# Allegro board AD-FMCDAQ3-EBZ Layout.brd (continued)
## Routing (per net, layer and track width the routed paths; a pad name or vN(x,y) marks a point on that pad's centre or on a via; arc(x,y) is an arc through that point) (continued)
P1V7: length 57.5
  TOP w0.305: U17.16 38,13.68 ; U17.16 U17.15 36.86,12.84 ; U17.16 37.51,12.84 ; U17.3 39.27,15.9 ; U17.3 U17.4 ; U17.3 U17.2 ; U19.1 U19.2 ; U19.1 16.47,63.53 ; U19.1 15.63,63.04 ; U19.2 U19.3 ; U19.2 15.63,62.39 ; U17.4 38.43,17.05 ; U17.4 39.27,16.55 ; U19.3 U19.4 ; U19.3 15.63,61.74 ; U19.4 15.63,61.09 ; U19.4 16.47,60.59 ; U17.2 39.27,15.25 ; U17.2 U17.1 ; 18.04,64.8 U19.15 U19.16 ; 16.9,63.96 U19.16 ; U19.16 17.39,64.8 ; U17.1 39.27,14.6 ; U17.1 38.43,14.11
  TOP w0.508: C167.P 41.64,14.18 ; C167.P 40.72,12.85 ; C167.P 39.81,14.18 ; C186.P 15.09,63.46 ; C186.P 14.18,64.79 ; C186.P 13.26,63.46
  L2_AGND w0.254: v1(43.89,67.13) v2(43.89,66.63)
  BOTTOM w0.508: CO5.2 59.95,31.2 ; CO5.2 58.63,30.08 ; CO5.2 58.63,32.32 ; CO5.2 57.31,31.2 ; RFB2.2 51.58,27.39 ; RFB2.2 51.58,25.36 ; RFB2.2 50.61,26.37 ; 48.6,27.71 TP3.1 ; TP3.1 49.29,28.41 ; TP3.1 48.6,29.11 ; TP3.1 47.9,28.41 ; 54.51,31.2 CO6.2 ; CO6.2 55.83,30.08 ; CO6.2 55.83,32.32 ; CO6.2 57.16,31.2 ; 48.92,31.2 CO8.2 ; CO8.2 51.57,31.2 ; CO8.2 50.25,32.32 ; CO8.2 50.25,30.08 ; 51.72,31.2 CO7.2 ; CO7.2 54.36,31.2 ; CO7.2 53.04,30.08 ; CO7.2 53.04,32.32
  BOTTOM w0.762: L12.2 59.9,29.76 ; L12.2 62.41,29.09 ; L12.2 59.9,27.68 ; L12.2 57.38,29.09
  vias: v1(13.8,64.22) v1(13.8,63.46) v1(13.8,62.7) v1(14.56,64.22) v1(14.56,63.46) v1(14.56,62.7) v1(39.58,12.28) v1(39.58,11.52) v1(40.34,12.28) v1(40.34,11.52) v1(41.1,12.28) v1(41.1,11.52) v1(41.86,12.28) v1(41.86,11.52) v2(12.27,64.22) v2(12.27,63.46) v2(12.27,62.7) v2(13.04,64.22) v2(13.04,63.46) v2(13.04,62.7) v2(37.67,11.01) v2(37.67,10.25) v2(38.44,11.01) v2(38.44,10.25) v2(39.2,11.01) v2(39.2,10.25) v2(39.96,11.01) v2(39.96,10.25) v2(47.96,34.38) v2(47.96,33.74) v2(47.96,33.11) v2(48.6,34.38) v2(48.6,33.74) v2(48.6,33.11) v2(49.23,34.38) v2(49.23,33.74) v2(49.23,33.11) v3(48.09,32.34) v3(48.09,31.71) v3(48.09,31.07) v3(48.09,30.44) v3(48.09,29.8) v3(48.72,32.34) v3(48.72,31.71) v3(48.72,31.07) v3(48.72,30.44) v3(48.72,29.8)
P2V5_EN: length 97.4
  TOP w0.152: v1(48.47,54.19) 48.47,52.16 48.71,51.92 U4.4
  TOP w0.305: U5.4 v4(8.15,7.24)
  L2_AGND w0.152: v1(48.47,54.19) v2(48.47,55.2)
  L3_SIG w0.254: v2(6.56,51.65) 6.56,43.77 10.94,39.39 10.94,11.45 8.72,9.23 8.72,7.8 v4(8.15,7.24)
  L8_SIG w0.254: v2(6.56,51.65) 8.21,53.3 23.7,53.3 24.72,54.31 28.15,54.31 31.09,57.26 33.79,57.26 34.57,56.47 43.01,56.47 44.28,55.2 v2(48.47,55.2)
P3V3_CLK_OUT: length 28.3
  TOP w0.254: C63.2 v1(37.86,33.23) 37.17,33.23 37.14,33.26 U7.42 ; U7.45 36.53,34.76 37.55,34.76 37.55,34.76 v1(37.86,34.76) C83.2 ; C59.2 v1(37.86,39.33) 37.29,39.33 37.22,39.26 U7.54 ; C66.2 v1(37.86,31.71) 37.81,31.76 36.53,31.76 U7.39 ; U7.27 31.33,29.47 C70.2 ; U7.48 36.53,36.26 37.55,36.26 37.57,36.28 v1(37.86,36.28) C82.2 ; C80.2 37.93,37.74 v1(37.86,37.74) 37.55,37.74 37.53,37.76 U7.51 ; U7.36 35.82,30.05 35.82,29.63
  TOP w0.305: U7.66 v4(30.33,39.11) ; v1(33.23,28.74) 32.86,28.74 C72.2 32.82,28.75 32.82,29.21 U7.30 ; U7.69 v4(28.83,39.11) ; U7.63 v4(31.83,39.11) ; 35.82,29.63 36.15,29.3 36.15,28.72 v1(36.28,28.72) ; U7.33 34.33,29.4 34.05,29.13 v1(34.05,28.72) ; U7.60 v4(33.33,39.11) ; C70.2 v1(32.11,28.74)
  TOP w1.016: C24.1 v1(37.29,25.61) 35.84,25.61 E11.2
  L2_AGND w0.254: v1(37.86,31.71) v2(37.36,31.77) ; v2(37.36,34.76) v1(37.86,34.76) ; v2(37.36,36.28) v1(37.86,36.28) ; v2(37.36,33.23) v1(37.86,33.23) ; v2(37.36,39.33) v1(37.86,39.33) ; v1(36.28,28.72) v2(36.28,29.17) ; v1(37.86,37.74) v2(37.36,37.74)
  L2_AGND w0.305: v2(32.11,29.26) v1(32.11,28.74) ; v2(33.23,29.26) v1(33.23,28.74)
  L2_AGND w0.356: v2(34.05,28.22) v1(34.05,28.72)
  BOTTOM w0.305: v4(30.33,39.11) 30.24,39.19 C78.2 ; C32.2 33.29,39.14 v4(33.33,39.11) ; v4(28.83,39.11) 28.85,39.13 C30.2 ; v4(31.83,39.11) 31.64,39.3 C79.2
  vias: v1(37.29,26.12) v1(37.29,25.1) v1(37.93,26.12) v1(37.93,25.61) v1(37.93,25.1) v2(36.4,27.77) v2(37.17,27.77) v2(37.93,27.77)
P3V3_CLK_PLL: length 9.4
  TOP w0.254: U7.16 26.63,31.76 25.79,31.76 25.61,31.58 C81.2 v1(25.23,31.58)
  TOP w0.305: v1(24.91,35.07) C71.2 25.54,35.07 25.86,34.76 U7.10 ; U7.1 26.63,39.58 v4(26.43,39.77) ; U7.20 27.83,29.04 C64.2 27.16,28.72 v1(27.13,28.75) ; U7.72 27.33,39.58 27.39,39.52 27.39,39.2 v4(27.48,39.11)
  L2_AGND w0.254: v1(25.23,31.58) v2(25.74,31.58)
  L2_AGND w0.305: v1(27.13,28.75) v2(27.13,29.22) ; v1(24.91,35.07) v2(25.42,35.07)
  BOTTOM w0.305: v4(27.48,39.11) 27.26,38.89 C73.2 ; C60.2 26.5,39.27 26.5,39.7 v4(26.43,39.77)
  vias: v1(22.18,29.8) v1(22.18,29.3) v1(22.69,29.8) v1(22.69,29.3) v2(21.29,28.79) v2(21.93,28.79) v2(22.56,28.79)
P3V6: length 87
  TOP w0.254: 7.45,42.76 7.45,42.88 7.66,43.1 7.88,43.1 8.05,43.27 8.59,43.27
  TOP w0.305: 11.23,24.1 U8.8 11.97,23.63 ; v1(53.17,52.03) 53.06,51.92 U4.3 ; 11.23,24.6 U8.7
  TOP w0.508: 8.74,23.52 C149.1 ; C149.1 9.86,24.48 ; C149.1 10.98,23.52 ; 49.42,39.93 U22.1 49.99,38.85 ; C262.1 50.86,41.93 ; C262.1 49.74,40.97 ; C262.1 48.62,41.93 ; C48.1 9.23,49.12 ; C48.1 8.11,48.15 ; C48.1 10.34,48.15 ; C34.1 12.88,48.15 ; C34.1 10.65,48.15 ; C34.1 11.77,49.12 ; 47.52,39.93 U22.3 46.95,38.85 ; 8.27,50.38 U10.8 ; U10.8 10.43,50.38 ; U10.8 9.35,49.74 ; C166.1 7.45,24.48 ; C166.1 8.57,23.52 ; C166.1 6.33,23.52 ; C163.1 48.32,41.93 ; C163.1 47.2,40.97 ; C163.1 46.08,41.93 ; 9.35,54.19 7.96,54.19
  L2_AGND w0.254: v1(54.56,67.13) v2(54.56,66.63) ; v1(53.17,52.03) v2(53.68,52.03)
  L3_SIG w0.508: v2(54.56,66.63) 53.04,65.11 53.04,59.78 54.06,58.76 54.06,57.11 53.68,56.73 v2(53.68,52.03)
  BOTTOM w0.508: 53.48,7.86 C152.1 ; C152.1 52.52,8.98 ; C152.1 53.48,10.09 ; 49.99,10.63 U11.5 51.07,9.99 ; 53.48,5.32 C18.1 ; C18.1 53.48,7.55 ; C18.1 52.52,6.44 ; 51.64,47.46 RFB1.2 52.98,48.92 ; 49.99,5.55 U11.8 51.07,6.18
  BOTTOM w0.635: CO4.2 54.74,50.63 ; CO4.2 52.1,50.63 ; CO4.2 53.42,49.51 ; CO4.2 53.42,51.75 ; 57.69,50.63 CO2.2 ; CO2.2 60.33,50.63 ; CO2.2 59.01,51.75 ; CO2.2 59.01,49.51 ; TP2.1 48.98,49.43 ; TP2.1 48.28,48.73 ; TP2.1 48.98,48.03 ; TP2.1 49.68,48.73 ; CO3.2 56.22,51.75 ; CO3.2 54.89,50.63 ; CO3.2 57.54,50.63 ; CO3.2 56.22,49.51 ; 60.48,50.63 CO1.2 ; CO1.2 61.8,49.51 ; CO1.2 61.8,51.75 ; CO1.2 63.12,50.63 ; L11.2 61.83,49.3 ; L11.2 61.07,47.71 ; L11.2 62.59,47.71
  vias: v1(6.18,25.61) v1(6.18,24.85) v1(6.94,25.61) v1(6.94,24.85) v1(7.7,25.61) v1(7.7,24.85) v1(8.72,48.47) v1(8.72,47.84) v1(9.73,48.47) v1(9.73,47.84) v1(11.26,48.47) v1(11.26,47.84) v1(12.27,48.47) v1(12.27,47.84) v1(49.23,40.22) v1(49.48,40.85) v1(50.12,40.85) v1(50.12,40.34) v1(50.12,39.84) v1(50.75,40.85) v1(50.75,40.34) v1(50.75,39.84) v2(6.18,24.22) v2(6.18,23.45) v2(6.94,24.22) v2(6.94,23.45) v2(7.7,24.22) v2(7.7,23.45) v2(8.72,49.11) v2(9.48,49.11) v2(10.24,49.11) v2(11,49.11) v2(11.77,49.11) v2(12.53,49.11) v2(47.96,41.11) v2(47.96,40.34) v2(47.96,39.58) v2(48.34,53.3) v2(48.34,52.54) v2(48.34,51.77) v2(48.72,41.11) v2(48.72,40.34) v2(48.72,39.58) v2(49.1,53.3) v2(49.1,52.54) v2(49.87,53.3) v2(49.87,52.54) v2(50.63,53.3) v2(50.63,52.54) v2(52.79,10.88) v2(52.79,10.12) v2(52.79,9.36) v2(53.55,10.88) v2(53.55,10.12) v2(53.55,9.36) v3(48.98,51.77) v3(48.98,51.01) v3(48.98,50.25) v3(49.74,51.77) v3(49.74,51.01) v3(49.74,50.25) v3(50.5,51.77) v3(50.5,51.01) v3(50.5,50.25) v3(51.26,10.88) v3(51.26,10.12) v3(51.26,9.36) v3(51.26,8.59) v3(52.02,10.88) v3(52.02,10.12) v3(52.02,9.36) v3(52.02,8.59) v4(6.69,42.76) v4(8.72,43.01) v4(9.48,43.01) v4(10.11,44.54) v4(10.11,43.77)
VINA1_N: length 10.3
  BOTTOM w0.254: 15.19,28.14 15.19,27.9 15.32,27.77 16.33,27.77 16.46,27.64 T100.5 ; 15.19,28.14 13.29,28.14 13.02,27.87 13.01,27.87 12.27,27.13 T101.1 ; 15.19,28.14 18.46,28.14 C187.1
VINA1_P: length 10
  BOTTOM w0.254: T100.3 13.92,29.17 14.05,29.04 15.07,29.04 15.19,28.91 15.19,28.65 ; 15.19,28.65 13.35,28.65 12.33,29.67 T101.3 ; 15.19,28.65 18.25,28.65 18.39,28.79 C108.1
VINA_N: length 2.8
  BOTTOM w0.203: U100.5 23.62,25.07 23.62,26.05 23.35,26.32 23.35,26.74 C196.1
  BOTTOM w0.254: C196.1 23.32,26.9 23.32,27.53 R109.2
VINA_P: length 2.8
  BOTTOM w0.203: U100.6 24.08,25.07 24.08,26.24 23.83,26.48 23.83,26.77 C196.2
  BOTTOM w0.254: C196.2 23.83,26.9 23.83,27.53 R108.2
VINB1_N: length 10.4
  BOTTOM w0.254: C118.1 18.65,12.46 18.07,13.04 15.19,13.04 ; T102.3 13.92,13.55 14.05,13.42 15.07,13.42 15.19,13.29 15.19,13.04 ; T103.3 12.15,14.05 13.16,13.04 15.19,13.04
VINB1_P: length 9.9
  BOTTOM w0.254: T103.1 12.14,11.51 13.16,12.53 15.19,12.53 ; 15.19,12.53 17.86,12.53 C188.1 ; 15.19,12.53 15.19,12.28 15.32,12.15 16.33,12.15 16.46,12.02 T102.5
VINB_N: length 2.3
  BOTTOM w0.203: C198.2 23.61,14.73 23.61,15.99 U100.44
  BOTTOM w0.254: R126.2 23.58,13.99 23.58,14.56 C198.2
VINB_P: length 2.3
  BOTTOM w0.203: U100.43 24.07,15.98 24.07,14.7 C198.1
  BOTTOM w0.254: C198.1 24.08,14.56 24.08,13.99 R127.2
3P3_SUP: length 85
  TOP w0.254: 71.07,43.65 71.09,43.63 U12.23 ; 71.07,43.65 C234.1 ; 71.07,43.65 71.07,43.27 71.21,43.13 U12.24 ; U13.24 71.21,28.78 71.07,28.91 71.07,29.3 ; U13.23 71.09,29.28 71.07,29.3 ; U9.6 73.19,19.56 v1(72.73,20.02) ; 71.07,29.3 C233.1
  TOP w0.508: 49.55,32.5 C261.1 ; C261.1 49.55,34.73 ; C261.1 v1(50.75,33.61) ; 48.85,36.51 U22.5 ; U22.5 49.99,36.51 ; U22.5 49.42,35.43 ; C68.P 43.83,14.63 45.36,14.63 C25.1 U14.1 ; U15.1 44.25,24.34 44.53,24.62 C28.1 45.04,26.76 v1(45.04,27.9)
  L2_AGND w0.254: v1(72.73,20.02) v2(72.09,20.02) ; v1(71.07,31.71) v2(71.71,31.07) ; v1(43.39,13.55) 43.39,12.53 v2(43.64,12.28) ; v1(43.9,53.3) v2(45.93,53.3) ; v1(71.07,46.06) v2(71.07,45.42)
  L2_AGND w0.305: v1(43.39,13.55) v1(43.39,14.82) ; v1(45.04,29.17) v1(45.04,27.9) v2(44.28,27.9)
  L3_SIG w0.305: v2(45.93,53.3) 45.93,51.9 47.2,50.63 47.2,38.06 50.37,34.88 v2(50.37,32.22) v2(50.37,31.33) ; v2(72.09,20.02) 71.71,20.41 v2(71.71,31.07) 71.33,31.45 71.33,39.71 71.71,40.09 71.71,44.79 v2(71.07,45.42)
  vias: v1(50.75,34.12) v1(50.75,33.11) v1(51.64,34.12) v1(51.64,33.61) v1(51.64,33.11) v2(49.48,32.22) v2(49.48,31.33)
3P3_XO: length 6.2
  TOP w0.381: v1(10.24,36.66) 10.3,36.72 C126.1
  TOP w0.508: Y1.6 12.07,36.66 v1(10.24,36.66) 10.24,34.88
  L2_AGND w0.305: v2(10.24,36.03) v1(10.24,36.66)
ADC_1P0: length 4.9
  L9_AGND w0.152: v3(27.1,25.71) 26.56,26.25 26.56,26.82 26.91,27.17 27.05,27.17 27.32,27.45 27.32,27.9 v3(26.88,28.34)
  BOTTOM w0.152: U100.12 v3(27.1,25.71) ; v3(26.88,28.34) C100.1
ADC_1P2_AVDD: length 21.3
  TOP w1.27: 25.23,6.94 v1(24.85,6.94) 23.33,6.94 E1.2
  L9_AGND w0.254: v3(20.4,26.12) v2(20.78,25.68) v3(21.16,26.12) ; v3(19.77,22.81) v2(20.21,22.5) ; v3(19.77,25.04) v2(20.21,24.85) ; v3(19.77,18.25) v2(20.27,18.25) ; v3(19.77,15.96) v2(20.27,15.96) ; v3(19.77,19.77) v2(20.27,19.77) ; v3(20.97,14.63) v2(21.35,14.18) v3(21.73,14.63)
  BOTTOM w0.254: C138.1 19.76,19.76 v3(19.77,19.77) 20.82,19.77 U100.55 ; U100.2 22.1,25.49 21.8,25.79 21.49,25.79 v3(21.16,26.12) 21.04,26.25 C135.1 ; 19.64,15.96 v3(19.77,15.96) 20.58,16.78 U100.49 ; C144.1 20.4,26.31 v3(20.4,26.12) 21.16,25.36 21.48,25.36 21.6,25.24 U100.1 ; 19.64,25.04 v3(19.77,25.04) 20.53,24.28 U100.64 ; 19.64,22.75 19.71,22.75 v3(19.77,22.81) 19.8,22.78 U100.61 ; U100.52 19.67,18.28 19.64,18.25
  BOTTOM w0.305: U100.47 22.1,15.24 21.93,15.07 C136.1 v3(21.73,14.63) ; U100.48 21.6,15.51 21.16,15.07 C145.1 v3(20.97,14.63)
  vias: v1(24.85,7.58) v1(24.85,6.31) v1(25.61,7.58) v1(25.61,6.94) v1(25.61,6.31) v2(24.21,7.58) v2(24.21,6.94) v2(24.21,6.31)
ADC_1P2_AVDD_SR: length 20.6
  TOP w1.27: 25.23,11.64 23.34,11.64 E2.2
  L3_SIG w0.508: v2(25.74,10.5) v2(25.1,10.5) 23.97,10.5 21.11,13.36 20.71,13.36 20.34,13.73 20.34,14.13 17.86,16.61 17.86,19.77 18.88,20.79 v2(20.27,20.79)
  L9_AGND w0.254: v3(19.77,20.79) v2(20.27,20.79)
  BOTTOM w0.254: U100.57 19.78,20.78 v3(19.77,20.79) 19.64,20.79
  vias: v1(24.72,11.9) v1(24.72,11.13) v1(25.35,11.9) v1(25.35,11.13)
ADC_1P2_DRVDD: length 12.4
  TOP w1.27: C232.1 v1(45.42,6.94) 43.92,6.94 E9.2
  L9_AGND w0.254: v3(33.61,16.34) v2(33.61,16.98) ; v3(33.61,25.1) v2(33.61,24.47)
  BOTTOM w0.254: U100.19 30.51,23.28 31.58,24.34 C209.1 C211.1 32.91,24.41 v3(33.61,25.1) ; U100.30 30.52,17.78 31.52,16.78 C210.1 C212.1 33.17,16.78 v3(33.61,16.34)
  vias: v1(45.42,6.31) v1(46.18,6.94) v1(46.18,6.31) v2(45.42,7.71) v2(46.18,7.71)
ADC_1P2_DVDD: length 7.8
  TOP w1.27: E3.2 33.63,6.94 v1(35.13,6.94) C227.1
  L9_AGND w0.254: v3(29.67,14.63) 28.72,14.63 v2(28.66,14.69) ; v3(29.35,26.31) 29.64,26.03 v2(30.11,26.03)
  BOTTOM w0.254: v3(29.35,26.31) C207.1 29.16,26.18 28.6,25.62 U100.15 ; U100.34 28.6,15.56 29.53,14.63 C153.1 v3(29.67,14.63)
  vias: v1(35.13,6.31) v1(35.9,6.94) v1(35.9,6.31) v2(35.13,7.71) v2(35.9,7.71)
ADC_2P5_AVDD: length 94
  TOP w1.27: E17.2 17.88,15.47 C96.P
  L2_AGND w0.254: v1(43.9,63.97) v2(43.39,63.97)
  L3_SIG w0.305: v2(25.67,26.12) 23.39,28.41 23.39,36.09 20.97,38.5 20.97,50.95 22.18,52.16 23.07,52.16 25.1,54.19 25.1,57.62 24.34,58.38 24.34,62.06 v2(25.1,62.82)
  L8_SIG w0.305: v2(43.39,63.97) 42.25,62.82 v2(25.1,62.82)
  L9_AGND w0.254: v3(26.12,26.69) 26.12,26.56 v2(25.67,26.12) 25.34,26.59 v3(25.35,26.69) ; v3(19.77,16.72) v2(20.21,17.1) v3(19.77,17.48) ; v3(27.77,26.76) v2(27.39,26.31) v3(27.07,26.76) ; v3(19.77,23.52) v2(20.21,23.9) v3(19.77,24.28) ; v2(26.74,14.11) v3(26.74,14.63) ; v3(22.5,14.63) v2(22.5,14.14) ; v3(26,14.63) v2(25.62,14.11) v3(25.25,14.63) ; v3(21.93,26.25) v2(21.93,25.55)
  BOTTOM w0.229: 26.88,26.76 26.88,26.73 26.18,26.03 26.18,25.93 26.1,25.85 U100.10
  BOTTOM w0.254: 19.64,17.48 v3(19.77,17.48) 20.06,17.78 U100.51 ; U100.3 22.6,25.53 21.93,26.2 v3(21.93,26.25) 21.8,26.37 C173.1 ; U100.39 26.1,15.28 26.56,14.82 C177.1 v3(26.74,14.63) ; 19.64,24.28 v3(19.77,24.28) 20.27,23.78 U100.63 ; U100.62 20.01,23.28 v3(19.77,23.52) 19.64,23.52 ; v3(25.25,14.63) C129.1 25.1,14.69 U100.41 ; U100.9 25.6,26.17 v3(26.12,26.69) C175.1 ; U100.40 25.6,14.99 25.8,14.79 C179.1 v3(26,14.63) ; C123.1 v3(25.35,26.69) 25.1,26.44 U100.8 ; U100.11 26.6,25.86 26.99,26.25 27.26,26.25 27.64,26.63 27.64,26.76 v3(27.77,26.76) ; v3(27.07,26.76) 26.88,26.76 ; 19.64,16.72 v3(19.77,16.72) 20.32,17.28 U100.50
  BOTTOM w0.305: v3(22.5,14.63) C130.1 22.6,14.72 U100.46
  vias: v1(17.35,16.09) v1(17.35,15.33) v1(17.86,16.09) v1(17.86,15.33) v1(18.37,16.09) v1(18.37,15.33) v2(17.99,14.69) v2(18.75,14.69) v2(18.75,13.93)
ADC_3P3_AVDD: length 10.7
  TOP w0.254: C143.1 v1(22.69,14.82)
  TOP w0.305: C142.1 v1(25.04,14.82)
  TOP w1.27: E20.2 v1(29.54,3.63) C181.1
  L2_AGND w0.305: v1(25.04,14.82) v2(25.11,15.4) ; v1(22.69,14.82) v2(22.59,15.39)
  L9_AGND w0.254: v3(22.69,26.25) v2(22.69,25.55) ; v3(24.6,15.4) v2(25.11,15.4) ; v3(24.59,26.18) v2(24.59,25.55) ; v3(23.1,15.39) v2(22.59,15.39)
  BOTTOM w0.254: U100.7 24.6,26.18 v3(24.59,26.18) C141.1 ; U100.45 v3(23.1,15.39) ; U100.4 23.1,25.84 v3(22.69,26.25) 22.56,26.37 C140.1 ; U100.42 v3(24.6,15.4)
  vias: v1(29.54,3) v1(30.43,3.63) v1(30.43,3) v2(29.55,4.4) v2(30.43,4.4)
ADC_3P3_SPIVDD: length 7
  TOP w1.27: C220.1 v1(36.4,3.63) E21.2
  L9_AGND w0.254: v3(27.51,14.61) 27.51,14.11 v2(27.53,14.09) ; v3(28.59,26.31) v2(28.85,25.74)
  BOTTOM w0.254: U100.13 27.6,25.86 27.98,26.25 28.34,26.25 C150.1 v3(28.59,26.31) ; U100.38 26.6,15.48 27.32,14.75 C151.1 27.5,14.63 v3(27.51,14.61)
  vias: v1(35.51,4.27) v1(35.51,3.63) v1(35.51,3) v1(36.4,4.27) v1(36.4,3) v2(35.51,4.91) v2(36.4,4.91)
ADC_CLK1_N: length 1.4
  TOP w0.254: C40.1 30.82,28.85 30.82,30.05 U7.26
ADC_CLK1_P: length 1.4
  TOP w0.254: U7.25 30.31,30.04 30.31,28.85 C41.1
ADC_CLK_FMC1_N: length 2.8
  TOP w0.203: U7.53 36.55,38.74 39.18,38.74 C168.1
ADC_CLK_FMC1_P: length 2.8
  TOP w0.203: C162.1 39.16,38.28 36.55,38.28 U7.52
ADC_CLK_FMC_N: length 30.4
  TOP w0.254: v4(42.91,29.42) 42.74,29.26 42.24,29.26 40.74,30.76 39.96,30.76 C174.2 ; P501.B21 v1(66.83,34.86)
  L2_AGND w0.254: v1(66.83,34.86) 66.72,34.74 66.03,34.74 v2(65.87,34.91)
  L3_SIG w0.254: v2(65.87,34.91) 65.71,34.76 65.28,34.76 62.1,31.58 52.19,31.58 50.42,29.8 46.23,29.8 45.72,29.3 43.03,29.3 v4(42.91,29.42)
ADC_CLK_FMC_P: length 30.4
  TOP w0.254: P501.B20 v1(66.83,34.12) ; v4(42.91,28.61) 42.77,28.75 42.03,28.75 40.53,30.25 39.96,30.25 C171.2
  L2_AGND w0.254: v1(66.83,34.12) 66.72,34.24 66.01,34.24 v2(65.87,34.1)
  L3_SIG w0.254: v4(42.91,28.61) 43.08,28.79 45.93,28.79 46.44,29.3 50.63,29.3 52.4,31.07 62.31,31.07 65.49,34.25 65.71,34.25 v2(65.87,34.1)
ADC_CLK_N: length 29.7
  TOP w0.254: v4(15.85,18.78) 15.57,18.5 15.09,18.5 14.84,18.75 14.84,19.14 15.41,19.71 17.37,19.71 19.51,21.85 19.51,25.74 20.66,26.88 30.05,26.88 30.51,27.34 31.04,27.34 31.25,27.54 31.25,27.87 31.03,28.09 C40.2
  BOTTOM w0.203: 19.04,19.26 20.81,19.26 U100.54
  BOTTOM w0.254: 19.04,19.26 17.67,19.26 17.17,18.75 16.52,18.75 R56.1 16.43,18.78 v4(15.85,18.78)
ADC_CLK_P: length 29.8
  TOP w0.254: v4(15.85,17.99) 14.88,17.99 14.33,18.54 14.33,19.35 15.2,20.21 17.16,20.21 19,22.06 19,25.95 20.44,27.39 29.8,27.39 30.18,27.77 C41.2
  BOTTOM w0.203: 19.28,18.75 19.33,18.8 20.8,18.8 U100.53
  BOTTOM w0.254: 19.28,18.75 17.88,18.75 17.38,18.25 16.53,18.25 R56.2 16.03,18.18 v4(15.85,17.99)
ADC_FDA: length 97.8
  L2_AGND w0.152: v1(74.76,32.47) v2(74.76,33.11)
  L3_SIG w0.152: v2(30.18,24.85) 30.18,25.23 26.24,29.17 26.24,35.39 25.16,36.47 25.16,44.17 25.63,44.64 25.63,50.91 v2(26.12,51.39) ; v2(72.6,49.62) 72.6,47.96 73.23,47.33 73.23,43.27 75.01,41.49 75.01,36.28 74.76,36.03 v2(74.76,33.11)
  L8_SIG w0.152: v2(72.6,49.62) 70.95,49.62 70.82,49.74 56.85,49.74 56.09,48.98 42.63,48.98 39.71,51.9 29.55,51.9 29.29,51.65 26.37,51.65 v2(26.12,51.39)
  L9_AGND w0.152: v2(30.18,24.85) 30.43,25.1 v3(30.94,25.1)
  BOTTOM w0.152: v3(30.94,25.1) 30.11,24.28 U100.17
ADC_FDB: length 93.3
  L2_AGND w0.152: v1(75.27,34.38) v2(75.27,35.01)
  L3_SIG w0.152: v2(73.74,46.19) 73.74,43.27 76.03,40.98 76.03,36.79 75.27,36.03 v2(75.27,35.01) ; v2(36.4,48.09) 36.91,47.58 37.55,47.58 38.31,46.82 38.31,41.87 35.64,39.2 35.64,27.26 31.32,22.95 v2(31.32,15.07)
  L8_SIG w0.152: v2(36.4,48.09) 36.91,47.58 37.67,47.58 38.77,46.49 50.93,46.49 52.41,47.96 55.33,47.96 57.92,45.37 69.3,45.37 70.87,46.95 72.98,46.95 v2(73.74,46.19)
  L9_AGND w0.152: v2(31.32,15.07) 30.94,15.45 v3(30.94,15.96)
  BOTTOM w0.152: v3(30.94,15.96) 30.57,16.33 30.13,16.78 U100.32
ADC_PD: length 74.4
  L2_AGND w0.152: v1(75.77,46.82) v2(75.77,47.46)
  L3_SIG w0.152: v2(25.86,41.55) 25.54,41.23 25.54,36.6 26.62,35.52 26.62,30.57 27.69,29.5 v2(27.69,28.41)
  L8_SIG w0.152: v2(25.86,41.55) 25.86,42.25 27.92,44.31 30.97,44.31 32.97,46.31 35.77,46.31 36.02,46.57 38.18,46.57 38.69,46.06 38.94,46.06 38.97,46.08 51.16,46.08 51.87,46.8 54.11,46.8 55.38,45.53 55.63,45.53 57.23,43.93 66.73,43.93 67.21,44.41 73.36,44.41 v1(75.77,46.82) v2(75.77,47.46)
  L9_AGND w0.152: v3(28.1,25.72) 28.1,26.45 28.21,26.56 28.21,26.95 27.69,27.47 v2(27.69,28.41)
  BOTTOM w0.152: U100.14 v3(28.1,25.72)
ADC_REFCLK_N: length 28.9
  TOP w0.254: v1(42.5,27.77) 42.25,27.52 42.14,27.52 41.49,28.17 40.14,28.17 40,28.03 C193.2 ; v1(60.03,17.13) 60.28,17.13 P501.G7
  L2_AGND w0.254: v2(58.45,17.13) 58.73,16.85 59.74,16.85 v1(60.03,17.13) ; v1(42.5,27.77) 42.74,27.53 43,27.53 43.77,26.76 43.99,26.76 v2(44.28,27.04)
  L3_SIG w0.254: v2(44.28,27.04) 44.52,26.79 45.27,26.79 48.26,23.81 52.7,23.81 56.34,20.17 56.34,17.57 57.04,16.87 58.19,16.87 v2(58.45,17.13)
ADC_REFCLK_P: length 28.7
  TOP w0.254: C194.2 39.15,27.39 39.25,27.49 39.46,27.49 39.49,27.52 40.21,27.52 40.35,27.66 41.28,27.66 41.92,27.01 42.36,27.01 v1(42.5,26.87) ; P501.G6 60.11,16.08 v1(60.03,16.16)
  L2_AGND w0.254: v1(42.5,26.87) 42.68,27.06 42.75,27.06 43.56,26.25 44.1,26.25 v2(44.28,26.07) ; v1(60.03,16.16) 59.84,16.34 58.63,16.34 v2(58.45,16.16)
  L3_SIG w0.254: v2(44.28,26.07) 44.5,26.28 45.06,26.28 48.05,23.3 52.49,23.3 55.83,19.96 55.83,17.36 56.82,16.37 58.19,16.37 58.21,16.34 58.26,16.34 v2(58.45,16.16)
ADC_SERDOUT0_N: length 2.8
  BOTTOM w0.203: U100.22 30.67,21.78 30.69,21.75 31.1,21.75 31.28,21.93 31.28,21.97
  BOTTOM w0.254: 31.28,21.97 31.68,22.38 32.34,22.38 C20.2
ADC_SERDOUT0_P: length 2.8
  BOTTOM w0.203: U100.23 30.67,21.28 30.69,21.3 31.29,21.3 31.6,21.61 31.64,21.61
  BOTTOM w0.254: C8.2 32.34,21.87 31.89,21.87 31.64,21.61
ADC_SERDOUT1_N: length 2.7
  BOTTOM w0.203: U100.24 30.67,20.78 30.69,20.75 31.35,20.75 31.55,20.95 31.7,20.95 31.73,20.98 31.75,20.98
  BOTTOM w0.254: 31.75,20.98 32.34,20.98 C85.2
ADC_SERDOUT1_P: length 2.6
  BOTTOM w0.203: U100.25 30.67,20.28 30.69,20.3 31.58,20.3 31.75,20.47
  BOTTOM w0.254: C84.2 32.34,20.47 31.75,20.47
ADC_SERDOUT2_N: length 2.6
  BOTTOM w0.203: 31.75,19.58 31.58,19.75 30.69,19.75 30.67,19.78 U100.26
  BOTTOM w0.254: C87.2 32.34,19.58 31.75,19.58
ADC_SERDOUT2_P: length 2.7
  BOTTOM w0.203: U100.27 30.67,19.28 30.69,19.3 31.35,19.3 31.55,19.1 31.7,19.1 31.73,19.07 31.75,19.07
  BOTTOM w0.254: 31.75,19.07 32.34,19.07 C86.2
ADC_SERDOUT3_N: length 2.8
  BOTTOM w0.203: 31.51,18.44 31.47,18.44 31.16,18.75 30.69,18.75 30.67,18.78 U100.28
  BOTTOM w0.254: C92.2 32.34,18.18 31.77,18.18 31.51,18.44
ADC_SERDOUT3_P: length 2.8
  BOTTOM w0.203: 31.15,18.08 31.15,18.12 30.97,18.3 30.69,18.3 30.67,18.28 U100.29
  BOTTOM w0.254: 31.15,18.08 31.56,17.67 32.34,17.67 C88.2
ADC_SPI_CSB: length 89.6
  L2_AGND w0.152: v2(75.27,49.36) v1(75.27,48.73)
  L3_SIG w0.152: v2(31.7,14.06) 31.32,14.44 31.2,14.44 30.82,14.82 30.82,22.95 35.26,27.39 35.26,39.46 37.93,42.12 37.93,45.74 35.9,47.77 35.9,48.35 36.15,48.6 38.56,48.6 v2(39.07,48.09)
  L8_SIG w0.152: v2(39.07,48.09) 40.59,48.09 41.84,46.85 50.65,46.85 52.15,48.35 55.58,48.35 58.22,45.7 68.92,45.7 72.06,48.85 74.76,48.85 v2(75.27,49.36)
  L9_AGND w0.152: v2(31.7,14.06) v3(31.07,14.06) 29.04,14.06 28.28,13.29 v3(28.25,13.29)
  BOTTOM w0.152: v3(28.25,13.29) 28.25,14.59 27.76,15.08 27.63,15.08 27.1,15.61 U100.37
ADC_SYNC_N: length 37.2
  TOP w0.254: P501.D9 v4(64.09,19.69)
  BOTTOM w0.203: 32.01,23.58 32.03,23.55 31.55,23.55 30.75,22.75 30.69,22.75 30.67,22.78 U100.20
  BOTTOM w0.254: 34.18,23.58 43.47,23.58 47.92,19.14 60.58,19.14 60.96,19.52 63.91,19.52 v4(64.09,19.69) ; 34.18,23.58 R72.1 34.05,23.58 ; 34.18,23.58 34.05,23.58 ; 34.05,23.58 32.01,23.58
ADC_SYNC_P: length 37.1
  TOP w0.254: P501.D8 v4(64.09,18.88)
  BOTTOM w0.203: U100.21 30.67,22.28 30.69,22.3 30.94,22.3 31.74,23.1 31.9,23.1 31.92,23.07
  BOTTOM w0.254: 34.18,23.07 43.26,23.07 47.71,18.63 60.79,18.63 61.17,19.01 63.96,19.01 v4(64.09,18.88) ; 34.18,23.07 34.05,23.07 ; 34.18,23.07 R72.2 34.05,23.07 ; 31.92,23.07 34.05,23.07
ADC_SYSREF1_N: length 2.8
  TOP w0.203: U7.50 36.55,37.24 39.2,37.24 C14.1
ADC_SYSREF1_P: length 2.8
  TOP w0.203: U7.49 36.55,36.78 39.14,36.78 C19.1
ADC_SYSREF_N: length 43.4
  TOP w0.254: C172.2 39.96,32.79 41.25,32.79 41.57,32.47 42.98,32.47 v4(43.29,32.78)
  L8_SIG w0.254: v4(43.29,32.78) 43.13,32.62 40.16,32.62 38.48,30.95 19.31,30.95 17.12,28.76 17.12,22.21 16.87,21.95 v4(16.41,21.95)
  BOTTOM w0.203: U100.59 20.82,21.77 19.28,21.77 19.26,21.8
  BOTTOM w0.254: 19.26,21.8 17.23,21.8 R55.1 17.09,21.8 16.57,21.8 v4(16.41,21.95)
ADC_SYSREF_P: length 43.5
  TOP w0.254: C15.2 39.96,32.28 41.04,32.28 41.36,31.96 v4(43.29,31.96)
  L8_SIG w0.254: v4(16.41,21.14) 16.72,21.45 17.08,21.45 17.63,22 17.63,22.42 17.63,28.55 19.52,30.44 38.69,30.44 40.37,32.11 43.13,32.11 v4(43.29,31.96)
  BOTTOM w0.203: 19.26,21.29 19.28,21.29 19.31,21.31 20.79,21.31 U100.58
  BOTTOM w0.254: 17.22,21.29 16.56,21.29 v4(16.41,21.14) ; 17.22,21.29 R55.2 ; 17.22,21.29 19.26,21.29
CLKD_SPI_CSB: length 108
  TOP w0.152: U7.21 28.33,30.06 v1(28.33,29.37)
  L2_AGND w0.152: v1(28.33,29.37) v2(28.15,29.8) ; v1(74.76,46.82) v2(74.76,47.46)
  L3_SIG w0.152: v2(74.76,47.46) 74.76,45.81 74.63,45.68 74.63,43.39 77.68,40.34 77.68,36.66 76.66,35.65 76.66,21.42 73.61,18.37 73.61,11.9 v2(72.09,10.37) ; v2(28.15,29.8) 28.15,28.34 28.82,27.67 29.2,27.67 30.61,26.26 30.61,25.37 30.88,25.1 30.88,24.66 29.55,23.33 29.55,14.31 v2(30.31,13.55)
  L8_SIG w0.152: v2(30.31,13.55) 30.94,12.91 30.94,11.9 31.45,11.39 32.97,11.39 34.5,12.91 44.4,12.91 45.67,11.64 53.68,11.64 55.71,9.61 70.19,9.61 70.95,10.37 v2(72.09,10.37)
  L9_AGND w0.152: v2(28.15,29.8) v3(29.61,29.99)
CLKD_STATUS0: length 51
  TOP w0.152: U7.56 35.33,39.96 35.33,40.54 35.64,40.85 39.96,40.85 41.1,42 41.1,43.01 v1(41.48,43.39)
  L2_AGND w0.152: v2(41.48,44.15) v1(41.48,43.39) ; v1(73.23,34.38) v2(73.23,35.01)
  L3_SIG w0.152: v2(73.11,42.12) 72.85,41.87 72.85,35.39 v2(73.23,35.01)
  L8_SIG w0.152: v2(41.48,44.15) 41.86,44.54 42.45,44.54 43.24,45.32 53.62,45.32 55.78,43.16 67.19,43.16 67.57,43.54 71.68,43.54 v2(73.11,42.12)
CLKD_STATUS1: length 51.6
  TOP w0.152: U7.55 35.83,40.28 36.02,40.47 40.39,40.47 41.86,41.94 41.86,43.01 v1(42.25,43.39)
  L2_AGND w0.152: v1(73.74,32.47) v2(73.74,33.11) ; v2(42.25,44.03) v1(42.25,43.39)
  L3_SIG w0.152: v2(73.36,41.11) 73.61,40.85 73.61,36.03 73.74,35.9 v2(73.74,33.11)
  L8_SIG w0.152: v2(42.25,44.03) 42.55,44.03 43.49,44.97 53.47,44.97 55.66,42.78 67.29,42.78 67.75,43.24 69.78,43.24 70.95,42.07 72.4,42.07 v2(73.36,41.11)
CLKD_SYSREF_ADC1_N: length 2.8
  TOP w0.203: C21.1 39.23,35.74 36.55,35.74 U7.47
CLKD_SYSREF_ADC1_P: length 2.8
  TOP w0.203: C17.1 39.12,35.28 36.55,35.28 U7.46
CLKD_SYSREF_ADC_N: length 30.4
  TOP w0.254: P501.G10 v4(60.15,20.94) ; C11.2 39.96,34.31 40.49,34.31 40.83,33.97 41.46,33.97 42.37,34.88 43.19,34.88 v4(43.29,34.98)
  L8_SIG w0.254: v4(60.15,20.94) 59.85,20.63 53.45,20.63 45.17,28.91 45.17,34.2 44.49,34.88 43.39,34.88 v4(43.29,34.98)
CLKD_SYSREF_ADC_P: length 30.4
  TOP w0.254: C16.2 39.96,33.8 40.28,33.8 40.62,33.46 41.67,33.46 42.58,34.38 43.08,34.38 v4(43.29,34.17) ; P501.G9 v4(60.15,20.13)
  L8_SIG w0.254: v4(43.29,34.17) 43.49,34.38 44.28,34.38 44.66,33.99 44.66,28.7 53.24,20.13 v4(60.15,20.13)
CLKD_SYSREF_DAC1_N: length 2.8
  TOP w0.203: C11.1 39.12,34.24 36.55,34.24 U7.44
CLKD_SYSREF_DAC1_P: length 2.8
  TOP w0.203: C16.1 39.22,33.78 36.55,33.78 U7.43
CLKD_SYSREF_DAC_N: length 29.2
  TOP w0.254: P501.H11 v4(58.83,22.21) ; v4(41.03,35.87) 40.86,35.71 39.96,35.71 C21.2
  L8_SIG w0.254: v4(58.83,22.21) 58.63,22.01 53.98,22.01 47.2,28.79 47.2,34.76 45.67,36.28 42.92,36.28 42.39,35.75 41.15,35.75 v4(41.03,35.87)
CLKD_SYSREF_DAC_P: length 29.2
  TOP w0.254: v4(41.03,35.06) 40.89,35.2 39.96,35.2 C17.2 ; P501.H10 v4(58.83,21.4)
  L8_SIG w0.254: v4(58.83,21.4) 58.81,21.4 58.7,21.5 53.77,21.5 46.69,28.58 46.69,34.55 45.46,35.77 43.13,35.77 42.6,35.24 41.2,35.24 v4(41.03,35.06)
DAC_1P2_CVDD12: length 19.4
  TOP w0.254: C9.4 27.87,54.44 28.05,54.26 28.05,53.12 v4(27.92,52.99) 27.49,53.43 C9.2 ; C9.6 v1(24.85,53.93) ; v2(25.74,52.92) v1(24.85,52.92) ; C90.2 v1(27.84,46.85)
  TOP w0.356: v4(27.54,48.09) 27.42,47.96 C97.2
  TOP w1.016: C231.1 E7.2
  L2_AGND w0.254: v2(27.84,46.39) v1(27.84,46.85) ; v1(24.85,53.93) 24.72,53.81 24.72,53.04 v1(24.85,52.92) v2(25.74,52.92)
  L9_AGND w0.254: v3(27.45,46.67) v2(27.84,46.39)
  BOTTOM w0.254: U1.56 27.5,51.09 C113.2 C120.2 27.17,52.24 v4(27.92,52.99) 28.52,52.99 C35.2 C104.2 29.46,52.81 U1.2 ; C38.2 v3(27.45,46.67) 27.53,46.59 U1.47 ; U1.50 v4(27.54,48.09)
  BOTTOM w0.356: C127.2 27.52,48.07 v4(27.54,48.09)
  vias: v1(25.1,57.62) v1(25.1,56.85) v1(25.1,56.09) v1(26.12,57.62) v1(26.12,56.85) v1(26.12,56.09) v2(25.99,55.46) v2(26.75,57.62) v2(26.75,56.98) v2(26.75,56.35) v2(26.75,55.71)
DAC_1P2_DVDD12: length 15.2
  TOP w0.254: C5.4 v1(36.53,57.24) ; C5.2 v1(36.53,56.22) ; C121.2 34.24,53.39 v4(33.74,52.89) 33.48,53.14 C128.2 ; v4(32.45,43.01) 32.6,42.85 C98.2 ; v1(33.67,55.73) 33.69,55.71 C5.8 ; C5.6 v1(33.67,56.73)
  TOP w1.016: C229.1 37.88,56.9 37.88,59.8 E5.2
  L2_AGND w0.254: v2(36.53,57.74) v1(36.53,57.24) 36.66,57.11 36.66,56.35 v1(36.53,56.22) ; v2(33.1,55.46) v1(33.67,55.73) v1(33.67,56.73)
  BOTTOM w0.254: U1.36 31.96,43.3 32.25,43.01 v4(32.45,43.01) ; v4(32.45,43.01) 32.46,43.03 U1.35 ; v4(32.45,43.01) 32.45,43 C114.2 ; v4(33.74,52.89) 33.96,52.66 U1.11
  vias: v1(37.42,57.62) v1(37.42,56.85) v1(37.42,56.09) v1(38.44,57.62) v1(38.44,56.85) v1(38.44,56.09) v2(37.42,58.25) v2(38.18,58.25) v2(38.94,58.25)
DAC_1P2_PVDD12: length 14.2
  TOP w0.254: C7.6 v1(32.97,56.22) ; C29.2 30.94,53.11 ; 30.94,53.11 C53.2 ; 30.94,53.11 v4(30.94,52.92) ; v1(32.97,57.16) 32.49,57.24 C7.8 ; C7.2 v1(29.8,56.73) ; C36.2 36.94,47.74 v4(37.29,48.09) 36.9,48.49 C49.2 ; C7.4 v1(29.8,55.71)
  TOP w1.016: E4.2 29.39,59.22 31.78,59.22 C228.1
  L2_AGND w0.254: v1(32.97,56.22) v2(32.97,56.7) v1(32.97,57.16) ; v1(29.8,56.73) 29.67,56.6 29.67,55.84 v1(29.8,55.71) v2(29.8,55.2)
  BOTTOM w0.254: v4(37.29,48.09) 37.29,48.09 U1.21 ; U1.5 30.96,52.9 v4(30.94,52.92)
  vias: v1(31.7,60.41) v1(31.7,59.93) v1(31.7,59.42) v1(32.29,60.44) v1(32.29,59.95) v1(32.29,59.42) v2(31.07,60.41) v2(31.07,59.88) v2(31.07,59.34)
DAC_1P2_SVDD12: length 50.5
  TOP w0: 37.03,42.19 C33.2 36.53,42.68 ; 35.77,42.83 C94.2 ; C101.2 35.31,42.62 ; C206.2 37.03,43.33 ; C43.2 36.26,42.68 ; C109.2 35.5,42.83
  TOP w0.254: C12.2 v1(37.17,43.14) ; C10.2 v1(40.21,53.43) ; C55.2 36.93,50.45 v4(37.3,50.09) 36.9,49.69 C52.2 ; C12.8 v1(40.21,43.65) ; C22.2 35.64,53.36 v4(35.64,52.92) ; C10.6 v1(37.17,53.93) ; C12.4 v1(37.17,42.12) ; C26.2 37.67,45.93 v4(37.29,45.55) 37.67,45.17 C204.2 ; C10.8 v1(37.17,52.92) ; C54.2 37.8,48.47 v4(38.18,48.09) 38.56,48.47 C50.2 ; C122.2 36.38,53.34 v4(36.38,52.92) ; C33.2 C43.2 v4(35.77,42.76) ; C47.2 37.66,47.46 v4(37.29,47.09) 37.69,46.69 C205.2 ; C109.2 35.01,42.88 34.88,42.76 35.01,42.63 35.01,42.38 34.82,42.19 C101.2 ; v1(40.01,42.73) 39.91,42.63 C12.6 ; C94.2 C206.2 v4(36.53,42.76) ; C10.4 v1(40.21,54.44) ; v4(34.88,52.92) 35.01,53.04 C37.2
  TOP w1.016: C230.1 40.04,45.86 40.04,48.75 E6.2
  L2_AGND w0.254: v1(37.17,42.12) 37.04,42.25 37.04,43.01 v1(37.17,43.14) v2(36.81,43.5) ; v1(40.21,53.43) 40.34,53.55 40.34,54.31 v1(40.21,54.44) v2(40.21,54.95) ; v2(37.17,52.41) v1(37.17,52.92) 37.04,53.04 37.04,53.81 v1(37.17,53.93) ; v1(40.21,43.65) 40.59,44.03 v2(40.72,44.03) 40.21,43.52 40.21,42.94 v1(40.01,42.73)
  BOTTOM w0: U1.31 34.93,43.15 ; U1.30 35.43,43.15 ; 34.99,43.15 U1.29
  BOTTOM w0.254: 34.88,42.76 34.46,43.17 U1.31 ; v4(37.29,45.55) 36.91,45.55 36.88,45.59 U1.26 ; U1.14 35.46,52.1 35.64,52.28 35.74,52.28 v4(36.38,52.92) 36.38,53.44 C56.2 ; U1.12 34.46,52.5 v4(34.88,52.92) C117.2 ; v4(37.3,50.09) U1.17 ; U1.13 34.96,52.24 v4(35.64,52.92) 35.67,52.94 C6.2 ; v4(36.53,42.76) 35.77,43.52 35.64,43.52 35.46,43.7 U1.29 ; U1.30 34.96,43.44 35.26,43.14 35.39,43.14 v4(35.77,42.76) ; v4(38.18,48.09) 37.66,48.61 36.19,48.61 U1.20 ; U1.23 v4(37.29,47.09)
  vias: v1(39.58,46.57) v1(39.58,45.81) v1(39.58,45.04) v1(40.59,46.57) v1(40.59,45.81) v1(40.59,45.04) v2(39.27,47.3) v2(39.93,47.3) v2(40.59,47.3)
DAC_3P3_AVDD33: length 21.9
  TOP w0.254: C160.2 27.28,48.61 v4(26.85,48.61) 26.85,49.17 C159.2 ; C157.2 v1(26.8,45.91) ; v3(23.07,53.93) v1(23.96,53.93) ; C46.2 27.2,50.25 ; 27.2,50.25 C161.2 ; 27.2,50.25 v4(27.01,50.25) ; CN4.4 v1(20.91,52.41) ; C156.2 26.19,44.4 v4(26.71,44.4) ; CN4.6 v1(23.96,52.92) ; CN4.2 v1(20.91,53.43)
  TOP w0.508: C44.1 13.67,40.98 v4(14.69,42) ; C42.1 v4(16.08,56.09)
  L2_AGND w0.254: v2(20.91,51.9) v1(20.91,52.41) 20.78,52.54 20.78,53.3 v1(20.91,53.43) ; v2(23.96,54.44) v1(23.96,53.93) 24.08,53.81 24.08,53.04 v1(23.96,52.92) ; v2(26.8,46.34) v1(26.8,45.91)
  L9_AGND w0.254: v3(27.16,46.02) v2(26.8,46.34) ; v3(23.07,39.96) v2(22.56,39.96) ; v3(23.07,58.25) v2(23.07,57.62) ; v3(23.07,35.65) v2(22.56,35.65) ; v3(23.07,53.93) v2(23.07,54.57)
  BOTTOM w0.254: v4(26.85,48.61) 26.87,48.62 28.22,48.62 U1.51 ; U1.46 27.22,46.09 v3(27.16,46.02) 27.14,46.01 C158.2 ; U1.54 27.17,50.09 v4(27.01,50.25) ; v4(26.71,44.4) C51.2 27.4,44.59 U1.43
  vias: v4(23.07,51.46) v4(23.07,50.82) v4(23.07,50.19) v4(23.07,49.55)
DAC_3P3_IOVDD33: length 9.3
  TOP w0.254: C57.2 34.05,43.33 ; 34.05,43.33 v1(34.12,43.27) ; 34.05,43.33 C58.2
  L2_AGND w0.254: v1(34.12,43.27) v2(33.48,43.27)
  L9_AGND w0.254: v3(36.15,59.39) v2(36.78,59.39) ; v3(33.99,42.76) v2(33.48,43.27) ; v3(27.86,42.9) v2(27.86,42.1)
  BOTTOM w0.254: U1.42 28.96,42.92 C191.2 C192.2 v3(27.86,42.9) ; R122.2 35.39,58.63 v3(36.15,59.39) ; U1.32 33.96,42.79 v3(33.99,42.76)
  vias: v1(21.16,41.87) v1(21.16,41.36) v1(21.16,40.85) v1(21.8,41.87) v1(21.8,41.36) v1(21.8,40.85) v2(22.43,42) v2(22.43,41.36) v2(23.07,42) v2(23.07,41.36)
DAC_CLK1_N: length 2
  TOP w0.203: U7.62 32.35,39.98 32.35,41.44 32.09,41.69 C1.1
DAC_CLK1_P: length 2.4
  TOP w0.203: U7.61 32.81,39.98 32.81,41.63 32.44,42 C3.1
DAC_CLK_FMC1_N: length 3
  TOP w0.203: U7.38 36.55,31.24 37.46,31.24 37.96,30.73 39.17,30.73 C174.1
DAC_CLK_FMC1_P: length 3
  TOP w0.203: C171.1 39.17,30.27 37.77,30.27 37.27,30.78 36.55,30.78 U7.37
DAC_CLK_FMC_N: length 43.7
  TOP w0.254: v4(43.52,40.29) 43.38,40.15 41.37,40.15 40.04,38.82 C168.2 ; P501.D5 v4(63.84,14.59)
  L8_SIG w0.254: v4(43.52,40.29) 43.72,40.09 44.38,40.09 48.32,36.15 49.48,36.15 51.9,33.74 51.9,26.88 53.55,25.23 58.76,25.23 62.06,21.93 62.06,15.33 62.95,14.44 63.68,14.44 v4(63.84,14.59)
DAC_CLK_FMC_P: length 43.8
  TOP w0.254: P501.D4 v4(63.84,13.78) ; v4(43.52,39.48) 43.52,39.52 43.39,39.65 41.58,39.65 40.2,38.26 39.97,38.26 C162.2
  L8_SIG w0.254: v4(63.84,13.78) 63.68,13.93 62.74,13.93 61.55,15.11 61.55,21.72 58.54,24.72 53.34,24.72 51.39,26.67 51.39,33.53 49.27,35.65 48.11,35.65 44.17,39.58 43.62,39.58 v4(43.52,39.48)
DAC_CLK_N: length 17.4
  TOP w0.254: v4(22.97,45.3) 22.97,44.58 24.81,42.73 31.03,42.73 31.53,42.23 C1.2
  BOTTOM w0.203: R14.2 25.87,47.57 28.24,47.57 U1.49
  BOTTOM w0.254: v4(22.97,45.3) 22.97,46.57 23.98,47.58 25.72,47.58 R14.2
DAC_CLK_P: length 16.9
  TOP w0.254: C3.2 31.88,42.6 31.68,42.8 31.68,43.06 31.5,43.24 25.02,43.24 23.49,44.77 23.49,45.01 v4(23.78,45.3)
  BOTTOM w0.203: U1.48 28.24,47.11 25.88,47.11 R14.1
  BOTTOM w0.254: R14.1 25.79,46.85 25.61,46.67 25.33,46.67 24.92,47.08 24.19,47.08 23.49,46.37 23.49,45.58 v4(23.78,45.3)
DAC_IRQ: length 61.8
  L2_AGND w0.152: v1(74.25,34.38) v2(74.25,35.01)
  L3_SIG w0.152: v2(74.25,35.01) 74.25,36.03 74,36.28 74,42 72.85,43.14 72.85,47.08 72.09,47.84 72.09,50 v2(72.6,50.5)
  L8_SIG w0.152: v2(33.99,54.82) 34.63,54.19 42.63,54.19 47.2,49.62 55.71,49.62 56.22,50.12 68.03,50.12 68.41,50.5 v2(72.6,50.5)
  L9_AGND w0.152: v3(33.99,54.31) v2(33.99,54.82)
  BOTTOM w0.152: v3(33.99,54.31) 33.24,53.57 33.24,52.65 33.46,52.43 U1.10
DAC_REFCLK_N: length 36.7
  TOP w0.254: P501.D21 64.3,35.18 v1(63.84,35.65) ; C185.2 v1(33.74,41.49)
  L2_AGND w0.254: v1(63.84,35.65) v2(63.33,35.65) ; v1(33.74,41.49) v2(33.74,42)
  L8_SIG w0.254: v2(33.74,42) 33.74,42.63 35.77,44.66 38.05,44.66 39.32,43.39 52.53,43.39 55.45,40.47 57.36,40.47 62.18,35.65 v2(63.33,35.65)
DAC_REFCLK_P: length 37
  TOP w0.254: v1(34.5,41.49) 34.37,41.36 C189.2 ; P501.D20 64.3,33.91 v1(63.84,34.38)
  L2_AGND w0.254: v1(34.5,41.49) v2(34.5,42) ; v1(63.84,34.38) v2(63.33,34.38)
  L8_SIG w0.254: v2(34.5,42) 34.29,42.21 34.29,42.46 35.98,44.15 37.84,44.15 39.11,42.88 52.32,42.88 55.24,39.96 57.15,39.96 61.97,35.14 62.95,35.14 63.07,35.01 63.45,35.01 63.58,34.88 63.58,34.63 v2(63.33,34.38)
DAC_SERDIN0_N: length 2.4
  BOTTOM w0.203: 37.47,50.57 37.44,50.59 36.17,50.59 U1.16
  BOTTOM w0.254: 37.47,50.57 38.44,50.57 C95.2
DAC_SERDIN0_P: length 2.4
  BOTTOM w0.203: U1.15 36.2,51.05 37.42,51.05 37.44,51.08 37.47,51.08
  BOTTOM w0.254: C93.2 38.44,51.08 37.47,51.08
DAC_SERDIN1_N: length 2.4
  BOTTOM w0.203: 37.52,49.08 37.49,49.08 37.47,49.11 36.18,49.11 U1.19
  BOTTOM w0.254: 37.52,49.08 38.4,49.08 C102.2
DAC_SERDIN1_P: length 2.4
  BOTTOM w0.203: U1.18 36.19,49.56 37.49,49.56 37.52,49.59
  BOTTOM w0.254: C99.2 38.47,49.59 37.52,49.59
DAC_SERDIN2_N: length 2.4
  BOTTOM w0.203: 37.65,46.57 37.63,46.57 37.6,46.54 36.21,46.54 U1.24
  BOTTOM w0.254: 37.65,46.57 38.44,46.57 C111.2
DAC_SERDIN2_P: length 2.4
  BOTTOM w0.203: 37.65,46.06 37.63,46.09 U1.25
  BOTTOM w0.254: 37.65,46.06 38.43,46.06 C110.2
DAC_SERDIN3_N: length 2.4
  BOTTOM w0.203: 37.6,45.09 37.57,45.07 36.18,45.07 U1.27
  BOTTOM w0.254: 37.6,45.09 38.42,45.09 C132.2
DAC_SERDIN3_P: length 2.4
  BOTTOM w0.203: U1.28 36.19,44.61 37.55,44.61 37.57,44.59 37.6,44.59
  BOTTOM w0.254: C124.2 38.45,44.59 37.6,44.59
DAC_SPI_CSB: length 61.7
  L2_AGND w0.152: v1(76.28,48.73) v2(76.28,49.36)
  L8_SIG w0.152: v4(26.75,41.74) 26.75,41.87 27.32,42.44 27.32,42.44 27.67,42.78 28.05,42.78 28.07,42.76 29.93,42.76 33.1,45.93 35.9,45.93 36.02,46.06 38.03,46.06 38.36,45.73 53.78,45.73 55.96,43.54 66.96,43.54 67.32,43.9 73.36,43.9 76.28,46.82 v2(76.28,49.36)
  BOTTOM w0.152: U1.41 29.46,42.04 29.27,41.84 27.89,41.84 27.79,41.74 v4(26.75,41.74)
DAC_SYNC_N: length 50.1
  TOP w0.254: v4(50.88,21.29) 51.19,20.99 52.08,20.99 52.72,20.34 52.72,19.71 52.72,19.45 54.96,17.22 55.57,17.22 56.33,17.98 59,17.98 59.22,18.21 P501.H8
  BOTTOM w0.254: U1.33 33.46,42.3 33.9,41.87 37.08,41.87 38.48,43.27 42.7,43.27 45.55,40.42 45.55,24.04 48.6,20.99 50.58,20.99 v4(50.88,21.29)
DAC_SYNC_P: length 50.1
  TOP w0.254: P501.H7 58.59,16.71 54.75,16.71 52.21,19.24 52.21,19.92 52.22,20.13 51.86,20.48 v4(50.88,20.48)
  BOTTOM w0.254: v4(50.88,20.48) 48.39,20.48 45.04,23.83 45.04,40.21 42.49,42.76 38.69,42.76 37.29,41.36 33.69,41.36 32.95,42.09 32.95,43.88 U1.34
DAC_SYSREF1_N: length 2.8
  TOP w0.203: C172.1 39.15,32.74 36.55,32.74 U7.41
DAC_SYSREF1_P: length 2.8
  TOP w0.203: C15.1 39.2,32.28 36.55,32.28 U7.40
DAC_SYSREF_N: length 40.3
  TOP w0.254: v4(41.76,38.08) 41.61,37.93 40.97,37.93 40.27,37.23 39.96,37.23 C14.2
  L3_SIG w0.254: v4(41.76,38.08) 41.46,37.78 40.75,37.78 40.21,38.31 40.21,44.71 42.5,46.99 42.5,49.44 40.3,51.65 36.61,51.65 36.11,52.16 32.55,52.16 31.96,52.75 31.96,57.18 32.11,57.34 32.36,57.34 32.52,57.49 32.52,57.77 v4(32.26,58.02)
  BOTTOM w0.203: R13.2 31.94,53.98 31.94,52.6 31.96,52.58 U1.7
  BOTTOM w0.254: R13.2 31.96,54.12 31.96,57.72 v4(32.26,58.02)
DAC_SYSREF_P: length 40.4
  TOP w0.254: C19.2 39.96,36.72 40.48,36.72 41.18,37.42 41.61,37.42 v4(41.76,37.27)
  L3_SIG w0.254: v4(31.45,58.02) 31.45,52.54 32.34,51.65 35.9,51.65 36.4,51.14 40.09,51.14 41.99,49.23 41.99,47.2 39.71,44.92 39.71,38.1 40.54,37.27 v4(41.76,37.27)
  BOTTOM w0.203: R13.1 31.48,53.96 31.48,52.6 31.46,52.58 U1.6
  BOTTOM w0.254: R13.1 31.45,54.12 v4(31.45,58.02)
DAC_TXEN: length 55.1
  L2_AGND w0.152: v1(76.79,46.82) v2(76.79,47.46)
  L8_SIG w0.152: v2(76.79,47.46) 76.79,50.38 75.9,51.27 68.66,51.27 67.9,50.5 55.96,50.5 53.55,52.92 51.77,52.92 51.39,53.3 51.39,53.81 50.88,54.31 44.15,54.31 42.75,55.71 34.12,55.71 33.23,54.82 32.97,54.82 v2(32.59,54.44)
  L9_AGND w0.152: v3(32.59,54.95) v2(32.59,54.44)
  BOTTOM w0.152: v3(32.59,54.95) 32.59,52.79 32.46,52.66 U1.8
DLOGIC_0: length 46.8
  TOP w0.152: U14.7 53.74,13.55 54.12,13.93 56.29,13.93 P501.K4 57.33,14.18 58.58,14.18 P501.H4 59.22,13.51 58.63,12.91 57.74,12.91 57.36,12.53 57.36,11.59 P501.J2 v1(58.08,11)
  L2_AGND w0.152: v1(66.84,28.78) 66.87,28.78 v2(67.26,29.17) ; v2(67.7,26.63) 68.09,26.24 v1(68.11,26.24) ; v2(67.37,13.01) v1(66.84,13.54) ; v1(66.84,18.62) 66.87,18.62 v2(67.26,18.22) ; v2(67.26,22.95) 66.84,23.36 v1(66.84,23.7) ; v1(58.08,11) 58.61,11 v2(58.62,11.01) ; v1(68.11,31.32) 68.09,31.32 v2(67.7,31.71)
  L3_SIG w0.152: v2(67.37,13.01) 68.03,13.67 68.03,14.94 67.26,15.71 v2(67.26,18.22) 67.77,18.73 67.77,19.77 67.26,20.28 v2(67.26,22.95) 67.9,23.58 67.9,25.87 67.7,26.07 v2(67.7,26.63) 68.28,27.21 68.28,28.15 v2(67.26,29.17) 67.9,29.8 67.9,30.69 67.7,30.9 v2(67.7,31.71)
  L8_SIG w0.152: v2(67.37,13.01) 67.09,13.29 65.36,13.29 63.45,11.39 59,11.39 v2(58.62,11.01)
DLOGIC_1: length 49.8
  TOP w0.152: U14.8 53.68,14.82 54.12,14.37 56.25,14.37 P501.K5 56.73,14.81 57.38,15.45 58.58,15.45 P501.H5 59.9,14.13 59.9,12.02 59.52,11.64 58.58,11.64 v1(57.95,12.27)
  L2_AGND w0.152: v1(57.95,12.27) 57.36,11.67 v2(57.36,11.01) ; v2(67.26,30.44) 66.87,30.05 v1(66.84,30.05) ; v2(67.26,19.49) 66.87,19.89 v1(66.84,19.89) ; v1(68.11,27.51) 68.09,27.51 v2(67.7,27.9) ; v1(66.84,24.97) 66.87,24.97 v2(67.26,24.57) ; v2(67.7,32.98) 68.09,32.59 v1(68.11,32.59) ; v2(67.48,14.81) v1(66.84,14.81)
  L3_SIG w0.152: v2(67.7,32.98) 67.01,32.29 67.01,30.69 v2(67.26,30.44) 67.26,30.06 66.76,29.55 66.76,28.84 v2(67.7,27.9) 67.7,27.57 67.14,27.01 67.14,25.87 67.26,25.74 v2(67.26,24.57) 67.26,24.09 66.76,23.58 66.76,20 v2(67.26,19.49) 67.26,19.01 66.76,18.5 66.76,15.53 v2(67.48,14.81)
  L8_SIG w0.152: v2(57.36,11.01) 58.12,11.77 63.33,11.77 66.36,14.81 v2(67.48,14.81)
EXT_TRIG_N: length 11.7
  TOP w0.254: U15.8 49.74,24.34 50.12,23.96 51.14,23.96 R35.2 51.9,23.96 53.02,23.96 54.29,25.23 55.64,25.23 56.02,25.61 58.6,25.61 P501.H14
EXT_TRIG_P: length 11.7
  TOP w0.254: P501.H13 58.59,24.33 56.1,24.33 55.71,24.72 54.5,24.72 53.23,23.45 51.9,23.45 R35.1 51.14,23.45 50.12,23.45 49.74,23.07 U15.7
FMC_3P3V: length 61.2
  TOP w0.254: 8.21,9.23 8.25,9.19 U5.1 9.1,9.86 9.1,9.86 ; 8.21,8.59 8.27,8.54 U5.2
  TOP w0.305: 8.26,8.69 U5.1 U5.2 ; U5.16 10.03,10.95 ; U5.16 U5.15 10.68,10.95 ; U5.16 9.53,10.11 ; U5.2 8.26,8.04 ; U5.2 U5.3 8.26,7.89 ; v1(47.45,51.9) 48.09,51.27 U4.5 49.74,51.27 49.99,51.52 49.99,52.92 49.48,53.43 R32.1
  TOP w0.508: 9.48,11.2 C31.P ; C31.P 8.56,12.53 ; C31.P 10.39,12.53
  L2_AGND w0.254: v1(51,67.13) v2(51,66.63) ; v1(47.45,51.9) v2(47.45,51.39)
  L3_SIG w0.305: v2(47.45,51.39) 46.56,52.28 46.56,66.63 47.2,67.27 48.21,67.27 48.86,66.63 v2(51,66.63)
  L8_SIG w0.305: v2(65.87,58.63) v2(64.98,58.63) v2(64.09,58.63) 63.45,59.27 55.45,59.27 52.15,62.57 50.37,62.57 49.87,63.08 49.87,65.49 v2(51,66.63)
  vias: v1(9.1,13.29) v1(9.1,12.53) v1(9.1,11.77) v1(9.86,13.29) v1(9.86,12.53) v1(9.86,11.77) v1(64.34,59.27) v1(64.34,56.73) v1(64.34,54.19) v1(65.61,58) v2(7.7,12.4) v2(7.7,11.77) v2(8.34,11.77) v4(66.88,67.01)
FMC_3P3VAUX: length 80.6
  TOP w0.254: C218.1 53.1,57.23 C217.2 50.73,57.75 U18.10 ; P501.D32 v1(64.95,49.74) ; U18.16 50.73,63.72 v1(50.49,63.96) 50.23,63.7 U18.17
  TOP w0.508: v1(71.07,62.06) 72.7,62.06 72.98,62.34 U2.8
  L2_AGND w0.254: v1(76.92,66.89) v2(76.92,66.38) ; v1(73.36,66.89) v2(73.36,66.38) ; v1(50.49,63.96) v2(50.49,63.45) ; v1(71.07,62.06) v2(71.07,61.55) ; v1(64.95,49.74) v2(64.47,49.23) ; v1(47.45,67.13) v2(47.45,66.63) ; v1(53.29,57.36) v2(53.29,57.86) ; v1(75.14,66.89) v2(75.14,66.38)
  L3_SIG w0.254: v2(76.92,66.38) v2(75.14,66.38) v2(73.36,66.38) 73.36,63.84 v2(71.07,61.55) 68.53,64.09 64.67,64.09 63.33,62.75 63.33,57.9 64.22,57.01 64.22,49.49 v2(64.47,49.23)
  L3_SIG w0.305: v2(53.29,57.86) 52.41,58.75 52.41,61.54 v2(50.49,63.45) 50.49,64.1 47.96,66.63 47.45,66.63 v2(47.45,66.63)
  L8_SIG w0.254: v2(50.49,63.45) 52.28,63.45 55.83,59.9 69.42,59.9 v2(71.07,61.55)
FMC_12P0V: length 36.6
  L2_AGND w0.254: v1(43.9,60.41) v2(44.4,60.41)
  L8_SIG w0.254: v2(44.4,60.41) 47.71,57.11 53.55,57.11 54.44,58 55.58,58 57.49,56.09 v2(65.23,56.09)
  BOTTOM w0.305: 74.71,65.31 UNK12P0V.1 ; UNK12P0V.1 75.82,66.43 ; UNK12P0V.1 74.71,66.43 ; UNK12P0V.1 75.82,65.31
  BOTTOM w0.508: 74.83,41.36 LIN2.1 ; LIN2.1 77.48,41.36 ; LIN2.1 76.15,42.3 ; LIN1.1 75.27,63.77 ; LIN1.1 73.94,62.83 ; LIN1.1 76.59,62.83 ; 72.37,63.31 C237.2 73.49,64.63
  vias: v1(65.57,55.45) v1(65.57,52.91) v2(65.23,54.7) v2(65.23,53.81) v2(66.12,56.09) v2(66.12,54.7) v2(66.12,53.81) v2(74.12,63.46) v2(74.12,62.7) v2(74.88,63.46) v2(74.88,62.7) v2(75.14,44.79) v2(75.14,44.03) v2(75.65,63.46) v2(75.65,62.7) v2(75.9,44.79) v2(75.9,44.03) v2(76.41,63.46) v2(76.41,62.7) v2(76.66,44.79) v2(76.66,44.03) v2(77.42,44.79) v2(77.42,44.03) v3(74,64.86) v3(74,64.09) v3(74.63,64.86) v3(74.63,64.09) v3(74.88,43.39) v3(74.88,42.63) v3(75.27,64.86) v3(75.27,64.09) v3(75.52,43.39) v3(75.52,42.63) v3(75.9,64.86) v3(75.9,64.09) v3(76.15,43.39) v3(76.15,42.63) v3(76.54,64.86) v3(76.54,64.09) v3(76.79,43.39) v3(76.79,42.63) v3(77.42,43.39) v3(77.42,42.63)
FMC_ADC_FDA: length 19.2
  L2_AGND w0.152: v1(74.5,24.6) v2(74.5,25.23) ; v1(58.93,28.76) v2(59.57,28.76)
  L8_SIG w0.152: v2(59.57,28.76) 60,28.33 61.39,28.33 61.5,28.23 64.01,28.23 65.46,29.68 70.57,29.68 74.5,25.74 v2(74.5,25.23)
FMC_ADC_FDB: length 22.5
  L2_AGND w0.152: v1(59.22,30.05) 59.27,30.05 v2(59.64,30.41) ; v1(75.01,22.69) v2(75.01,23.33)
  L8_SIG w0.152: v2(75.01,23.33) 75.01,25.74 70.79,29.96 65.33,29.96 63.94,28.56 61.63,28.56 61.52,28.66 60.61,28.66 60.25,29.02 60.25,29.81 v2(59.64,30.41)
FMC_ADC_PD: length 32.4
  L2_AGND w0.152: v2(65.16,21.52) 65.52,21.16 v1(65.57,21.16) ; v1(75.52,38.95) v2(75.52,39.58)
  L8_SIG w0.152: v2(65.16,21.52) 66.4,20.28 69.68,20.28 70.06,20.66 73.49,20.66 74,20.15 75.27,20.15 76.28,21.17 76.28,35.9 75.52,36.66 v2(75.52,39.58)
FMC_ADC_SPI_CSB: length 18.5
  TOP w0.152: v1(69.93,28.41) 69.93,34.41 71.17,35.65 72.85,35.65 73.49,36.28 74.19,36.28 R89.1
  L2_AGND w0.152: v1(69.93,28.41) 69.9,28.41 v2(69.51,28.8) ; v1(64.34,27.51) 64.39,27.51 v2(64.76,27.88)
  L8_SIG w0.152: v2(64.76,27.88) 65.28,28.41 69.12,28.41 v2(69.51,28.8)
FMC_CLK_DIR: length 5.1
  TOP w0.152: P501.B1 66.84,4.7 R19.2
FMC_CLKD_SPI_CSB: length 32.8
  L2_AGND w0.152: v1(64.3,22.43) 64.35,22.43 v2(64.72,22.79) ; v1(74.5,38.95) v2(74.5,39.58)
  L8_SIG w0.152: v2(64.72,22.79) 66.86,20.66 69.55,20.66 69.93,21.04 73.61,21.04 74.12,20.53 75.14,20.53 75.9,21.29 75.9,35.77 74.5,37.17 v2(74.5,39.58)
FMC_CLKD_STATUS0: length 14.7
  L2_AGND w0.152: v1(72.98,22.69) v2(72.98,22.06) ; v1(60.49,23.7) v2(60.91,24.34)
  L8_SIG w0.152: v2(72.98,22.06) 70.41,22.06 68.71,23.76 64.75,23.76 64.44,23.45 61.8,23.45 v2(60.91,24.34)
FMC_CLKD_STATUS1: length 14.1
  L2_AGND w0.152: v1(60.49,24.97) 60.54,24.97 v2(60.91,25.33) ; v1(73.49,24.6) v2(73.49,25.23)
  L8_SIG w0.152: v2(60.91,25.33) 61.14,25.1 68.28,25.1 68.53,24.85 73.11,24.85 v2(73.49,25.23)
FMC_DAC_IRQ: length 19.6
  L2_AGND w0.152: v1(60.49,27.51) 60.54,27.51 v2(60.91,27.87) ; v1(74,22.69) v2(74,23.33)
  L8_SIG w0.152: v2(60.91,27.87) 61.58,27.21 63.91,27.21 64.19,27.49 64.19,28 64.9,28.71 68.43,28.71 68.99,29.27 70.46,29.27 74,25.74 v2(74,23.33)
FMC_DAC_SPI_CSB: length 19.4
  TOP w0.152: v1(69.93,26.88) 70.44,27.39 70.44,29.04 70.31,29.17 70.31,34.25 71.33,35.26 72.98,35.26 73.61,35.9 74.82,35.9 R90.1
  L2_AGND w0.152: v1(69.93,26.88) 69.9,26.88 v2(69.51,27.28) ; v2(66.03,26.61) 65.66,26.24 v1(65.61,26.24)
  L8_SIG w0.152: v2(66.03,26.61) 66.69,27.28 v2(69.51,27.28)
FMC_DAC_TXEN: length 22.7
  L2_AGND w0.152: v1(76.54,38.95) v2(76.54,39.58) ; v1(60.49,28.78) 60.54,28.78 v2(60.91,29.14)
  L8_SIG w0.152: v2(60.91,29.14) 61.55,29.14 61.8,28.89 63.86,28.89 65.33,30.36 65.33,31.81 73.74,40.22 75.9,40.22 v2(76.54,39.58)
FMC_GA0: length 31.2
  TOP w0.152: U18.11 53.41,60.04 54.69,58.76 v1(54.69,56.6)
  L2_AGND w0.152: v1(74.5,54.06) v2(74.5,54.57) ; v2(64.98,51.52) 65.46,51.52 v1(65.57,51.64) ; v1(54.69,56.6) v2(54.69,57.11)
  L8_SIG w0.152: v2(74.5,54.57) 73.87,53.93 72.34,53.93 71.71,54.57 68.66,54.57 65.61,51.52 v2(64.98,51.52) 64.09,51.52 60.53,55.08 56.72,55.08 v2(54.69,57.11)
FMC_GA1: length 28.6
  TOP w0.152: U18.13 53.05,61.04 55.45,58.63 v1(55.45,56.6)
  L2_AGND w0.152: v1(64.3,52.91) 64.19,52.79 v2(63.71,52.79) ; v1(72.73,54.06) v2(72.73,54.57) ; v1(55.45,56.6) v2(55.45,57.11)
  L8_SIG w0.152: v2(55.45,57.11) 56.98,55.58 60.91,55.58 v2(63.71,52.79) 66.12,52.79 68.41,55.08 72.22,55.08 v2(72.73,54.57)
FMC_PG_C2M: length 56.6
  TOP w0.152: P501.D1 v1(65.56,8.47)
  L2_AGND w0.152: v1(65.56,8.47) v2(65.56,7.96)
  L3_SIG w0.152: v2(65.56,7.96) 67.42,9.81 67.42,12.18 69.37,14.13 69.37,15.71 69.63,15.96 69.63,22.44 68.28,23.78 68.28,26.63 68.66,27.01 68.66,29.47 69.58,30.39 69.58,31.12 69.27,31.43 68.79,31.43 68.58,31.63 68.58,32.38 v4(69.05,32.84) 69.88,33.68 69.88,38.74 69.55,39.07 69.55,52.16 v4(71.33,53.93)
  BOTTOM w0.254: v4(71.33,53.93) 70.81,53.42 U6.20 ; U3.20 68.54,32.33 v4(69.05,32.84)
FMC_SCL: length 54.6
  TOP w0.152: U18.15 52.64,62.04 v1(53.42,62.82) ; U2.6 75.52,64.22 75.14,64.6 v1(75.14,65.49) R28.2
  L2_AGND w0.152: v1(75.14,65.49) v2(74.63,65.49) ; v1(53.42,62.82) v2(53.8,63.2) ; v1(65.57,46.56) v2(66.21,46.56)
  L3_SIG w0.152: v2(66.21,46.56) 65.7,46.05 63.08,46.05 62.18,46.95 62.18,55.93 58.85,59.27 55.96,59.27 53.8,61.43 v2(53.8,63.2)
  L8_SIG w0.152: v2(74.63,65.49) 73.23,65.49 72.33,64.59 65.04,64.59 64.17,63.71 54.31,63.71 v2(53.8,63.2)
FMC_SDA: length 52.6
  TOP w0.152: U18.14 53.03,61.54 v1(54.31,62.82) ; R30.2 v1(76.92,65.49) 76.92,64.35 76.79,64.22 U2.5
  L2_AGND w0.152: v1(65.57,47.83) v2(66.08,47.83) ; v1(76.92,65.49) v2(76.41,65.49) ; v1(54.31,62.82) v2(54.31,62.32)
  L3_SIG w0.152: v2(54.31,62.32) 54.31,61.43 56.09,59.65 59.01,59.65 62.57,56.09 62.57,50.38 64.22,48.73 65.18,48.73 v2(66.08,47.83)
  L8_SIG w0.152: v2(76.41,65.49) 75.77,64.86 73.23,64.86 72.55,64.17 65.38,64.17 64.42,63.2 55.2,63.2 v2(54.31,62.32)
FMC_SERDIN0_N: length 34.7
  TOP w0.254: P501.A31 v4(68.59,47.2)
  BOTTOM w0.254: C95.1 43.18,50.5 48.89,44.79 68.01,44.79 68.59,45.37 v4(68.59,47.2)
FMC_SERDIN0_P: length 34.7
  TOP w0.254: P501.A30 v4(67.77,47.2)
  BOTTOM w0.254: v4(67.77,47.2) 67.47,47.2 67.31,47.05 67.31,46.7 67.49,46.52 67.87,46.52 68.08,46.31 68.08,45.58 67.8,45.3 49.1,45.3 43.39,51.01 39.43,51.01 39.3,51.14 C93.1
FMC_SERDIN1_N: length 34.1
  TOP w0.254: P501.A27 v4(67.72,42.1)
  BOTTOM w0.254: v4(67.72,42.1) 67.44,42.1 67.29,42.25 67.29,42.55 67.47,42.73 67.87,42.73 68.03,42.88 68.03,43.21 67.82,43.42 48.06,43.42 42.37,49.11 39.43,49.11 C102.1
FMC_SERDIN1_P: length 34
  TOP w0.254: P501.A26 v4(68.53,42.1)
  BOTTOM w0.254: C99.1 42.58,49.62 48.27,43.93 68.03,43.93 68.53,43.42 v4(68.53,42.1)
FMC_SERDIN2_N: length 35.6
  TOP w0.254: P501.A23 v4(68.53,37.04)
  BOTTOM w0.254: C111.1 39.2,46.57 43.34,46.57 47.54,42.38 65.74,42.38 68.53,39.58 v4(68.53,37.04)
FMC_SERDIN2_P: length 35.6
  TOP w0.254: P501.A22 v4(67.72,37.04)
  BOTTOM w0.254: C110.1 39.2,46.06 43.13,46.06 47.33,41.87 65.53,41.87 68.03,39.37 68.03,38.01 67.82,37.8 67.52,37.8 67.29,37.58 67.29,37.19 67.44,37.04 v4(67.72,37.04)
FMC_SERDIN3_N: length 63.7
  TOP w0.254: P501.C3 v4(65.97,11.64)
  BOTTOM w0.254: v4(65.97,11.64) 65.97,12.23 67.47,13.73 68.61,13.73 69.8,14.92 69.8,22.67 68.49,23.99 63.9,23.99 63.4,23.48 48.57,23.48 46.94,25.1 46.94,40.94 42.79,45.09 39.21,45.09 C132.1
FMC_SERDIN3_P: length 63.8
  TOP w0.254: P501.C2 v4(65.16,11.64)
  BOTTOM w0.254: v4(65.16,11.64) 64.88,11.64 64.7,11.82 64.7,12.1 64.95,12.35 65.38,12.35 67.26,14.23 68.4,14.23 69.3,15.13 69.3,22.46 68.28,23.48 64.11,23.48 63.61,22.97 48.36,22.97 46.44,24.89 46.44,40.73 42.58,44.59 39.18,44.59 C124.1
